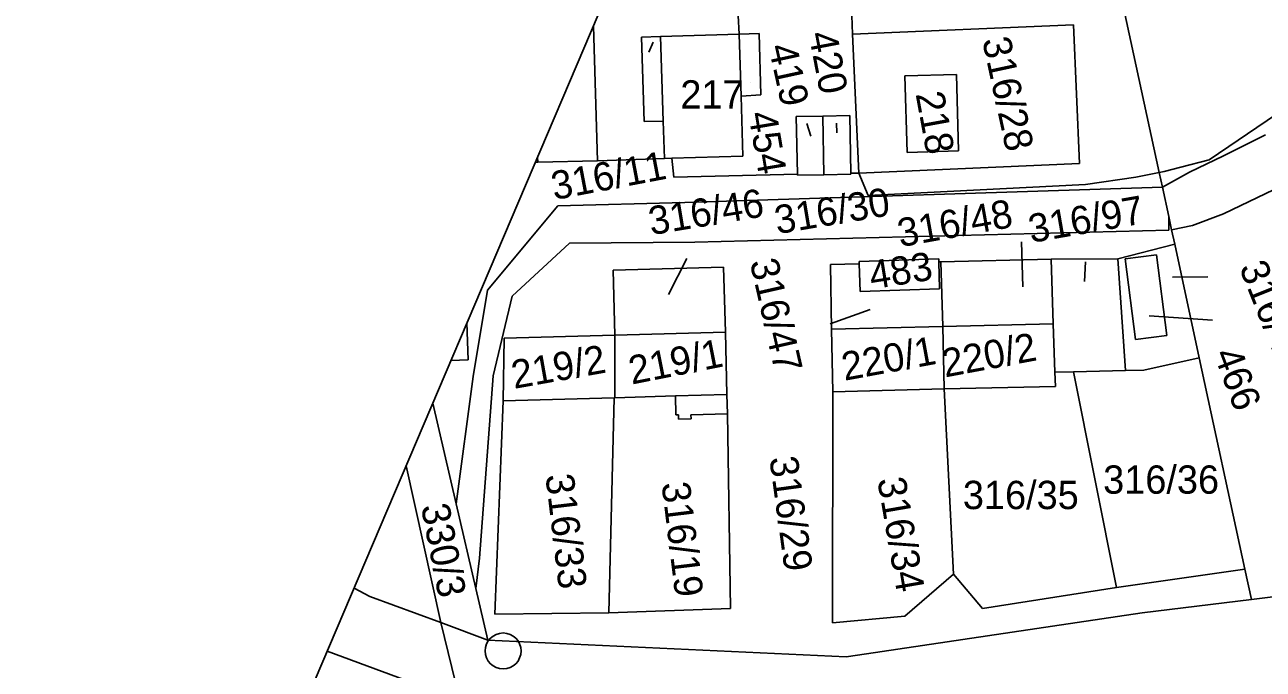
# Model space of a CAD drawing. Extents: x -805826 to -803822, y -1165880 to -1164382.
# Drawn here: x -805745.9 to -805597.3, y -1164897.7 to -1164820.3 of the extents above; entities that cross this region are included whole.
import ezdxf

# ---------------------------------------------------------------- set-up
doc = ezdxf.new("R2010")
doc.units = 0
for name, color, linetype in [('formát', 7, 'Continuous'), ('kilometráž - 2880', 7, 'Continuous'), ('kn_celek - Cisla parcel pomocna', 7, 'Continuous'), ('kn_celek - Cisla pozemkovych parcel', 7, 'Continuous'), ('kn_celek - Cisla stavebnich parcel', 7, 'Continuous'), ('kn_celek - Hranice parcel', 7, 'Continuous'), ('kn_celek - Vnitrni kresby', 7, 'Continuous'), ('plochy - SZDC', 7, 'Continuous')]:
    doc.layers.add(name, color=color, linetype=linetype)

msp = doc.modelspace()

# ---------------------------------------------------------------- linework, layer by layer
at = {"layer": 'formát'}
msp.add_line((-805491.17, -1164382.07), (-805826.05, -1165169.15), dxfattribs=at)
at = {"layer": 'kilometráž - 2880'}
msp.add_circle((-805688.53, -1164895.51), 2.16, dxfattribs=at)
at = {"layer": 'kn_celek - Cisla parcel pomocna'}
for p, q in [((-805671.05, -1164823.62), (-805670.54, -1164822.41)), ((-805658.86, -1164827.3), (-805658.86, -1164827.31)), ((-805648.49, -1164833.31), (-805648.52, -1164832.16)), ((-805651.6, -1164833.7), (-805652.1, -1164832.2)), ((-805626.16, -1164851.81), (-805626.34, -1164846.4)), ((-805668.69, -1164852.7), (-805666.5, -1164848.41)), ((-805618.76, -1164851.17), (-805618.65, -1164848.81)), ((-805608.22, -1164850.63), (-805603.97, -1164850.61)), ((-805644.5, -1164854.51), (-805649.29, -1164856.25)), ((-805611, -1164855.27), (-805603.42, -1164855.8))]:
    msp.add_line(p, q, dxfattribs=at)
at = {"layer": 'kn_celek - Hranice parcel'}
for p, q in [((-805609.8, -1164838.08), (-805616.42, -1164807.4)), ((-805647.01, -1164810.45), (-805646.59, -1164821.44)), ((-805660.61, -1164813.52), (-805660.2, -1164821.47)), ((-805677.7, -1164820.48), (-805677.21, -1164836.67)), ((-805669.63, -1164821.74), (-805671.93, -1164821.81)), ((-805660.2, -1164821.47), (-805669.63, -1164821.74)), ((-805669.32, -1164831.89), (-805669.63, -1164821.74)), ((-805657.8, -1164821.39), (-805660.2, -1164821.47)), ((-805660.2, -1164821.47), (-805659.97, -1164828.89)), ((-805657.61, -1164828.76), (-805657.8, -1164821.39)), ((-805646.59, -1164821.44), (-805620.08, -1164820.34)), ((-805646.59, -1164821.44), (-805645.86, -1164838.13)), ((-805620.08, -1164820.34), (-805619.36, -1164836.97)), ((-805671.93, -1164821.81), (-805671.6, -1164831.96)), ((-805640.33, -1164826.47), (-805634.14, -1164826.31)), ((-805640.04, -1164835.65), (-805640.33, -1164826.47)), ((-805634.14, -1164826.31), (-805633.91, -1164835.47)), ((-805659.97, -1164828.89), (-805657.61, -1164828.76)), ((-805659.75, -1164836.1), (-805659.97, -1164828.89)), ((-805671.6, -1164831.96), (-805669.32, -1164831.89)), ((-805669.18, -1164836.37), (-805669.32, -1164831.89)), ((-805653.37, -1164831.35), (-805650.15, -1164831.29)), ((-805653.37, -1164831.35), (-805653.22, -1164838.28)), ((-805650.15, -1164831.29), (-805646.91, -1164831.22)), ((-805650.15, -1164831.29), (-805650.04, -1164838.33)), ((-805646.8, -1164838.15), (-805646.91, -1164831.22)), ((-805595.74, -1164831.06), (-805603.81, -1164836.55)), ((-805684.39, -1164836.19), (-805684.37, -1164836.84)), ((-805677.21, -1164836.67), (-805669.18, -1164836.37)), ((-805669.18, -1164836.37), (-805668.28, -1164836.35)), ((-805668.28, -1164836.35), (-805659.75, -1164836.1)), ((-805668.28, -1164836.35), (-805668.05, -1164838.61)), ((-805633.91, -1164835.47), (-805640.04, -1164835.65)), ((-805603.81, -1164836.55), (-805607.21, -1164837.44)), ((-805684.37, -1164836.84), (-805684.67, -1164836.85)), ((-805684.37, -1164836.84), (-805677.21, -1164836.67)), ((-805645.86, -1164838.13), (-805619.36, -1164836.97)), ((-805612.62, -1164838.62), (-805609.8, -1164838.08)), ((-805609.21, -1164837.93), (-805609.8, -1164838.08)), ((-805609.8, -1164838.08), (-805609.43, -1164839.81)), ((-805607.21, -1164837.44), (-805609.21, -1164837.93)), ((-805668.05, -1164838.61), (-805653.22, -1164838.28)), ((-805653.22, -1164838.4), (-805653.22, -1164838.28)), ((-805650.04, -1164838.33), (-805653.22, -1164838.4)), ((-805646.81, -1164838.27), (-805650.04, -1164838.33)), ((-805646.81, -1164838.27), (-805646.8, -1164838.15)), ((-805646.8, -1164838.15), (-805645.86, -1164838.13)), ((-805645.86, -1164838.13), (-805644.74, -1164840.82)), ((-805644.74, -1164840.82), (-805618.66, -1164839.49)), ((-805618.66, -1164839.49), (-805612.62, -1164838.62)), ((-805609.43, -1164839.81), (-805666.71, -1164841.67)), ((-805609.43, -1164839.81), (-805608.67, -1164843.35)), ((-805595.02, -1164839.63), (-805602.1, -1164843.02)), ((-805690.38, -1164852.19), (-805681.95, -1164842.05)), ((-805681.95, -1164842.05), (-805666.71, -1164841.67)), ((-805608.65, -1164845), (-805608.67, -1164843.35)), ((-805608.32, -1164844.95), (-805608.67, -1164843.35)), ((-805605.83, -1164844.44), (-805602.1, -1164843.02)), ((-805665.52, -1164846.42), (-805608.65, -1164845)), ((-805608.32, -1164844.95), (-805605.83, -1164844.44)), ((-805607.94, -1164846.68), (-805608.32, -1164844.95)), ((-805687.44, -1164852.91), (-805680.58, -1164846.55)), ((-805680.58, -1164846.55), (-805665.52, -1164846.42)), ((-805614.77, -1164848.44), (-805607.94, -1164846.68)), ((-805607.94, -1164846.68), (-805605.02, -1164860.3)), ((-805636.24, -1164848.45), (-805645.81, -1164848.75)), ((-805636.24, -1164848.79), (-805636.24, -1164848.45)), ((-805636, -1164848.78), (-805622.76, -1164848.46)), ((-805622.76, -1164848.46), (-805614.77, -1164848.44)), ((-805622.76, -1164848.46), (-805622.52, -1164856.23)), ((-805613.85, -1164861.84), (-805614.77, -1164848.44)), ((-805613.88, -1164848.44), (-805610.13, -1164847.96)), ((-805612.64, -1164858.12), (-805613.88, -1164848.44)), ((-805610.13, -1164847.96), (-805608.88, -1164857.63)), ((-805675.34, -1164849.81), (-805662.08, -1164849.44)), ((-805675.13, -1164857.61), (-805675.34, -1164849.81)), ((-805662.08, -1164849.44), (-805661.86, -1164857.22)), ((-805649.25, -1164849.11), (-805645.8, -1164849.03)), ((-805649.25, -1164849.11), (-805649.11, -1164856.89)), ((-805645.81, -1164848.75), (-805645.8, -1164849.03)), ((-805645.8, -1164849.03), (-805645.7, -1164852.34)), ((-805636.24, -1164848.79), (-805636, -1164848.78)), ((-805636.16, -1164852.04), (-805636.24, -1164848.79)), ((-805636, -1164848.78), (-805635.79, -1164856.55)), ((-805692.12, -1164862.57), (-805690.38, -1164852.19)), ((-805689.72, -1164862.47), (-805687.44, -1164852.91)), ((-805645.7, -1164852.34), (-805636.16, -1164852.04)), ((-805692.86, -1164856.1), (-805692.72, -1164860.57)), ((-805661.86, -1164857.22), (-805675.13, -1164857.61)), ((-805661.69, -1164864.72), (-805661.86, -1164857.22)), ((-805649.11, -1164856.89), (-805635.79, -1164856.55)), ((-805649.11, -1164856.89), (-805648.98, -1164864.39)), ((-805635.79, -1164856.55), (-805622.52, -1164856.23)), ((-805635.79, -1164856.55), (-805635.6, -1164864.03)), ((-805622.52, -1164856.23), (-805622.32, -1164862.05)), ((-805688.38, -1164857.94), (-805688.52, -1164865.46)), ((-805675.13, -1164857.61), (-805688.38, -1164857.94)), ((-805675.13, -1164857.61), (-805675.12, -1164865.1)), ((-805608.88, -1164857.63), (-805612.64, -1164858.12)), ((-805611.64, -1164861.79), (-805605.02, -1164860.3)), ((-805605.02, -1164860.3), (-805599.54, -1164885.7)), ((-805692.72, -1164860.57), (-805694.79, -1164860.65)), ((-805620.1, -1164861.99), (-805613.85, -1164861.84)), ((-805613.85, -1164861.84), (-805611.64, -1164861.79)), ((-805692.12, -1164862.57), (-805694.16, -1164877.84)), ((-805689.72, -1164862.47), (-805691.34, -1164884.37)), ((-805622.32, -1164862.05), (-805620.1, -1164861.99)), ((-805622.32, -1164862.05), (-805622.26, -1164863.75)), ((-805614.95, -1164887.88), (-805620.1, -1164861.99)), ((-805661.61, -1164867.05), (-805661.69, -1164864.72)), ((-805649.02, -1164892.12), (-805648.98, -1164864.39)), ((-805648.98, -1164864.39), (-805635.6, -1164864.03)), ((-805635.6, -1164864.03), (-805622.26, -1164863.75)), ((-805634.48, -1164886.29), (-805635.6, -1164864.03)), ((-805694.16, -1164877.84), (-805696.97, -1164865.76)), ((-805688.52, -1164865.46), (-805689.51, -1164891.1)), ((-805688.52, -1164865.46), (-805675.22, -1164865.11)), ((-805675.22, -1164865.11), (-805675.83, -1164890.95)), ((-805675.22, -1164865.11), (-805675.12, -1164865.1)), ((-805675.12, -1164865.1), (-805667.85, -1164864.87)), ((-805667.79, -1164867.18), (-805667.85, -1164864.87)), ((-805667.48, -1164867.18), (-805667.79, -1164867.18)), ((-805667.47, -1164867.7), (-805667.48, -1164867.18)), ((-805665.97, -1164867.65), (-805667.47, -1164867.7)), ((-805665.99, -1164867.17), (-805661.61, -1164867.05)), ((-805665.99, -1164867.17), (-805665.97, -1164867.65)), ((-805661.61, -1164867.05), (-805661.25, -1164890.4)), ((-805696.01, -1164892.11), (-805700.17, -1164873.29)), ((-805691.79, -1164888.01), (-805694.16, -1164877.84)), ((-805691.34, -1164884.37), (-805691.79, -1164888.01)), ((-805634.48, -1164886.29), (-805640.34, -1164891.32)), ((-805634.48, -1164886.29), (-805631, -1164890.4)), ((-805599.54, -1164885.7), (-805614.95, -1164887.88)), ((-805598.76, -1164889.34), (-805599.54, -1164885.7)), ((-805704.5, -1164888.96), (-805706.41, -1164887.96)), ((-805690.35, -1164894.21), (-805691.79, -1164888.01)), ((-805631, -1164890.4), (-805614.95, -1164887.88)), ((-805598.76, -1164889.34), (-805583.88, -1164887.5)), ((-805704.5, -1164888.96), (-805696.01, -1164892.11)), ((-805598.76, -1164889.34), (-805611.85, -1164890.95)), ((-805689.51, -1164891.1), (-805675.83, -1164890.95)), ((-805661.25, -1164890.4), (-805675.83, -1164890.95)), ((-805640.34, -1164891.32), (-805649.02, -1164892.12)), ((-805611.85, -1164890.95), (-805645.99, -1164896.01)), ((-805696.01, -1164892.11), (-805690.35, -1164894.21)), ((-805647.35, -1164896.2), (-805690.35, -1164894.21)), ((-805709.64, -1164895.55), (-805693.71, -1164901.4)), ((-805647.35, -1164896.2), (-805645.99, -1164896.01))]:
    msp.add_line(p, q, dxfattribs=at)
at = {"layer": 'kn_celek - Vnitrni kresby'}
for p, q in [((-805602.11, -1164836.05), (-805597.07, -1164833.55)), ((-805606.16, -1164838.02), (-805602.11, -1164836.05)), ((-805609.43, -1164839.81), (-805606.16, -1164838.02)), ((-805667.85, -1164864.87), (-805661.69, -1164864.72))]:
    msp.add_line(p, q, dxfattribs=at)
at = {"layer": 'plochy - SZDC'}
for p, q in [((-805583.88, -1164887.5), (-805598.76, -1164889.34)), ((-805598.76, -1164889.34), (-805611.85, -1164890.95)), ((-805611.85, -1164890.95), (-805645.99, -1164896.01)), ((-805696.01, -1164892.11), (-805693.71, -1164901.4)), ((-805690.35, -1164894.21), (-805696.01, -1164892.11)), ((-805696.01, -1164892.11), (-805693.71, -1164901.4)), ((-805647.35, -1164896.2), (-805690.35, -1164894.21)), ((-805645.99, -1164896.01), (-805647.35, -1164896.2))]:
    msp.add_line(p, q, dxfattribs=at)

# ---------------------------------------------------------------- texts
at = {"layer": 'kn_celek - Cisla parcel pomocna'}
for s, rotation, p in [('420', 280.863, (-805651.89, -1164821.42)), ('419', 282.294, (-805656.7, -1164822.96)), ('454', 279.657, (-805659.12, -1164830.98)), ('316/46', 9.45, (-805670.77, -1164845.6)), ('316/97', 9.855, (-805625.19, -1164846.53)), ('316/48', 10.197, (-805640.88, -1164847.04)), ('316/47', 282.816, (-805658.95, -1164848.78)), ('316/44', 291.807, (-805600.26, -1164849.46)), ('466', 290.376, (-805603.31, -1164859.84))]:
    msp.add_text(s, height=3.4, rotation=rotation, dxfattribs=at).set_placement(p)
at = {"layer": 'kn_celek - Cisla pozemkovych parcel'}
for s, rotation, p in [('316/28', 282.186, (-805631.07, -1164822.15)), ('316/11', 10.773, (-805682.4, -1164841.39)), ('316/30', 9.513, (-805655.65, -1164845.48)), ('316/29', 277.713, (-805656.59, -1164872.33)), ('316/33', 276.795, (-805683.46, -1164874.41)), ('316/34', 279.837, (-805643.65, -1164874.92)), ('316/19', 276.966, (-805669.53, -1164875.39)), ('330/3', 280.9614, (-805698.4, -1164878.13))]:
    msp.add_text(s, height=3.4, rotation=rotation, dxfattribs=at).set_placement(p)
for s, height, p in [('316/97', 0.005, (-805618.76, -1164851.17)), ('316/44', 0.005, (-805608.22, -1164850.63)), ('316/46', 0.005, (-805668.69, -1164852.7)), ('316/48', 0.005, (-805626.16, -1164851.81)), ('316/47', 0.005, (-805644.5, -1164854.51)), ('316/36', 3.4, (-805616.54, -1164876.63)), ('316/35', 3.4, (-805633.37, -1164878.48))]:
    msp.add_text(s, height=height, dxfattribs=at).set_placement(p)
at = {"layer": 'kn_celek - Cisla stavebnich parcel'}
for s, height, p in [('453', 0.005, (-805671.05, -1164823.62)), ('217', 3.4, (-805667.26, -1164830.39)), ('454', 0.005, (-805658.86, -1164827.3)), ('420', 0.005, (-805648.49, -1164833.31)), ('419', 0.005, (-805651.6, -1164833.7)), ('466', 0.005, (-805611, -1164855.27))]:
    msp.add_text(s, height=height, dxfattribs=at).set_placement(p)
for s, rotation, p in [('218', 280.404, (-805639.05, -1164828.63)), ('483', 9.171, (-805644.31, -1164852.11)), ('220/2', 10.602, (-805635.51, -1164862.68)), ('219/2', 10.08, (-805687.21, -1164864.05)), ('219/1', 11.169, (-805673.1, -1164863.53)), ('220/1', 10.431, (-805647.58, -1164863.08))]:
    msp.add_text(s, height=3.4, rotation=rotation, dxfattribs=at).set_placement(p)

doc.saveas('drawing.dxf')
